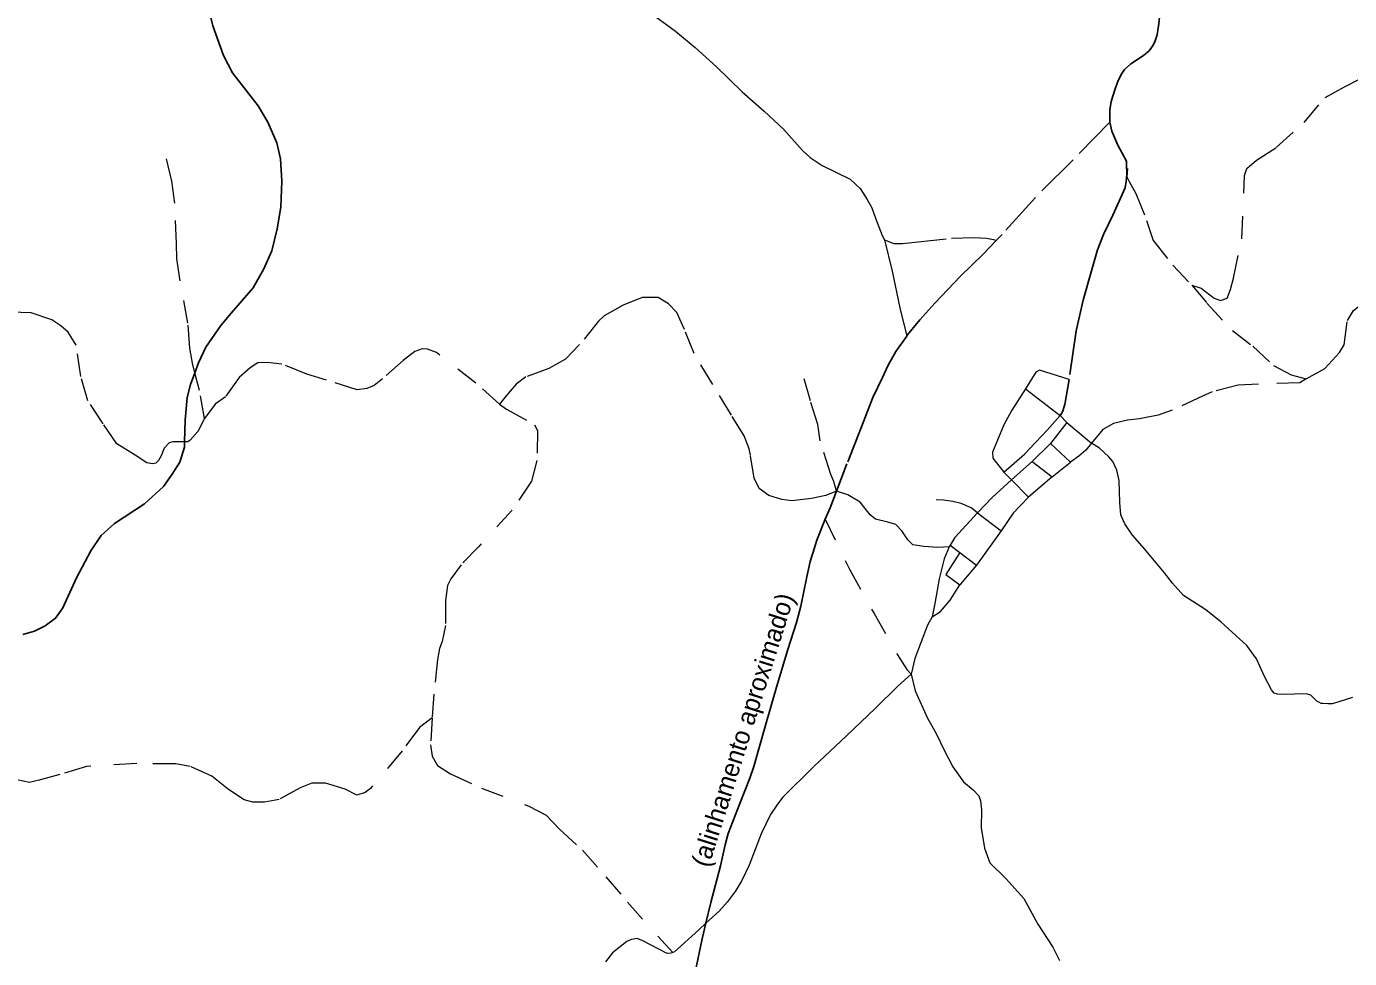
# Model space of a CAD drawing. Extents: x 703.1 to 728.9, y 7316.2 to 7344.3.
# Drawn here: x 708.41 to 714.18, y 7328.43 to 7332.5 of the extents above; entities that cross this region are included whole.
import ezdxf
from ezdxf.enums import TextEntityAlignment as Align

# ---------------------------------------------------------------- set-up
doc = ezdxf.new("R2010")
doc.units = 0
doc.header["$LTSCALE"] = 0.032
for name, pattern in [('DOTTED', [1.5, 0.3, -1.2]), ('LONG_DASHED', [7.5, 6, -1.5]), ('MEDIUM_DASHED', [4.5, 3, -1.5])]:
    doc.linetypes.add(name, pattern=pattern)
for name, color, linetype, lineweight in [('15', 7, 'Continuous', 25), ('4', 7, 'LONG_DASHED', 25), ('5', 7, 'LONG_DASHED', 13), ('6', 7, 'MEDIUM_DASHED', 13), ('7', 7, 'DOTTED', 13), ('8', 7, 'Continuous', 13)]:
    doc.layers.add(name, color=color, linetype=linetype, lineweight=lineweight)
doc.layers.add('61', color=7, linetype='Continuous')

msp = doc.modelspace()

# ---------------------------------------------------------------- linework, layer by layer
at = {"layer": '15'}
for points in [[(709.277, 7332.7781), (709.2015, 7332.6379), (709.1977, 7332.6052), (709.2236, 7332.505), (709.2701, 7332.3753), (709.3092, 7332.2997), (709.4206, 7332.1555), (709.4634, 7332.0838), (709.5024, 7331.9943), (709.5188, 7331.9238), (709.5244, 7331.8261), (709.5194, 7331.714), (709.5043, 7331.6183), (709.481, 7331.5233), (709.4457, 7331.4439), (709.3991, 7331.3608), (709.3035, 7331.2512), (709.2575, 7331.1965), (709.1933, 7331.102), (709.1606, 7331.034), (709.1445, 7330.9905)], [(709.1445, 7330.9905), (709.1259, 7330.9401), (709.1108, 7330.8834), (709.102, 7330.7839), (709.0995, 7330.6892)], [(709.0995, 7330.6892), (709.0989, 7330.6662), (709.0788, 7330.6007), (709.046, 7330.5478), (709.0083, 7330.4949), (708.9245, 7330.4188), (708.7949, 7330.3331), (708.7357, 7330.2802), (708.6904, 7330.2135), (708.628, 7330.0957), (708.5689, 7329.9647), (708.5374, 7329.9194), (708.4921, 7329.8866), (708.4448, 7329.8633), (708.3945, 7329.8482)]]:
    msp.add_lwpolyline(points, dxfattribs=at)
at = {"layer": '4'}
for points in [[(713.3572, 7332.6135), (713.3518, 7332.5254), (713.3422, 7332.4651), (713.3337, 7332.439), (713.3242, 7332.42), (713.307, 7332.3959), (713.2823, 7332.3756), (713.2278, 7332.3388), (713.1995, 7332.3134), (713.1881, 7332.2969), (713.1729, 7332.2658), (713.1589, 7332.2303), (713.1421, 7332.1744), (713.1358, 7332.1376), (713.1358, 7332.0843)], [(713.1358, 7332.0843), (712.9756, 7331.92), (712.8116, 7331.7557), (712.666, 7331.5946), (712.6412, 7331.5688)], [(713.1358, 7332.0843), (713.1448, 7332.0445), (713.1705, 7331.9832), (713.2087, 7331.914), (713.2096, 7331.8456)], [(713.2096, 7331.8456), (713.2131, 7331.882), (713.2078, 7331.827), (713.2025, 7331.7977), (713.1483, 7331.6778), (713.1088, 7331.5944), (713.0822, 7331.5269), (713.0529, 7331.4257), (713.0196, 7331.3068), (712.9895, 7331.1736), (712.958, 7330.9615)], [(712.6412, 7331.5688), (712.5819, 7331.507), (712.4842, 7331.4125), (712.3723, 7331.2938), (712.3066, 7331.2222), (712.2533, 7331.1555), (712.2501, 7331.1509)], [(712.2501, 7331.1509), (712.2029, 7331.0832), (712.1693, 7331.0236), (712.1439, 7330.9703), (712.1018, 7330.8821), (712.0631, 7330.7805), (711.9892, 7330.5934), (711.9434, 7330.4746), (711.9432, 7330.474)], [(712.958, 7330.9615), (712.9398, 7330.8514), (712.9301, 7330.8203), (712.9188, 7330.8043)], [(711.9432, 7330.474), (711.9153, 7330.4017), (711.8947, 7330.3511)], [(711.8947, 7330.3511), (711.8575, 7330.2597), (711.8398, 7330.2032), (711.829, 7330.167), (711.8138, 7330.1004), (711.7874, 7329.9716), (711.7687, 7329.9012), (711.7307, 7329.7826), (711.6815, 7329.6189), (711.6323, 7329.4475), (711.5825, 7329.2724), (711.5656, 7329.2217), (711.5219, 7329.1113), (711.4708, 7328.9799), (711.4577, 7328.9305), (711.4381, 7328.8385), (711.3952, 7328.6786), (711.3742, 7328.5886)], [(711.3742, 7328.5886), (711.3581, 7328.5199), (711.3217, 7328.3467)]]:
    msp.add_lwpolyline(points, dxfattribs=at)
at = {"layer": '5'}
for points in [[(711.112, 7332.5758), (711.2414, 7332.4815), (711.3273, 7332.4096), (711.4196, 7332.3256), (711.5315, 7332.2161), (711.6274, 7332.1322), (711.7124, 7332.0531), (711.7947, 7331.9603), (711.8291, 7331.93), (711.8806, 7331.8956), (712.0036, 7331.8357), (712.0468, 7331.7941), (712.0771, 7331.747), (712.0971, 7331.711), (712.1143, 7331.6646), (712.1423, 7331.5903), (712.1535, 7331.5711)], [(712.1535, 7331.5711), (712.1934, 7331.5543), (712.231, 7331.5543), (712.4451, 7331.5783), (712.5462, 7331.5815), (712.5982, 7331.5783), (712.6212, 7331.5732), (712.6412, 7331.5688)], [(712.1535, 7331.5711), (712.1859, 7331.4336), (712.2198, 7331.2737), (712.2501, 7331.1509)], [(714.1951, 7329.574), (714.1345, 7329.5546), (714.1059, 7329.5461), (714.0865, 7329.5461), (714.065, 7329.548), (714.0583, 7329.548), (714.0376, 7329.5595), (714.0122, 7329.5844), (713.9933, 7329.5899), (713.889, 7329.5862), (713.8677, 7329.5874), (713.8532, 7329.5923), (713.841, 7329.6069), (713.811, 7329.6651), (713.7758, 7329.7429), (713.7342, 7329.7999), (713.622, 7329.9025), (713.5549, 7329.9566), (713.4578, 7330.0185), (713.4099, 7330.0726), (713.375, 7330.1175), (713.287, 7330.2219), (713.2351, 7330.2821), (713.2011, 7330.3312), (713.1841, 7330.3701), (713.1789, 7330.4242), (713.1765, 7330.5207), (713.1665, 7330.5657), (713.1483, 7330.6027), (713.1319, 7330.624), (713.0912, 7330.6616), (713.0563, 7330.6841)], [(712.3603, 7329.9261), (712.3412, 7329.8886), (712.3125, 7329.8158), (712.2853, 7329.7444), (712.2692, 7329.676)], [(712.2692, 7329.676), (712.2118, 7329.6223), (712.1144, 7329.5266), (711.9864, 7329.4052), (711.8441, 7329.2721), (711.7084, 7329.1368), (711.6838, 7329.1037), (711.6558, 7329.0633), (711.6147, 7328.9787), (711.5629, 7328.8418), (711.5294, 7328.772), (711.5022, 7328.7271), (711.467, 7328.6807), (711.4321, 7328.6418), (711.3742, 7328.5886)], [(712.2692, 7329.676), (712.2871, 7329.6033), (712.3404, 7329.483), (712.3771, 7329.4187), (712.4129, 7329.3443), (712.4515, 7329.2709), (712.4979, 7329.2048), (712.5401, 7329.1699), (712.564, 7329.1451), (712.5722, 7329.123), (712.5768, 7329.0826), (712.575, 7329.0046), (712.5892, 7328.9155), (712.6122, 7328.8521), (712.6829, 7328.7833), (712.7614, 7328.6961), (712.822, 7328.584), (712.8867, 7328.4839), (712.917, 7328.4251)], [(711.3742, 7328.5886), (711.3431, 7328.5601), (711.2369, 7328.463), (711.2292, 7328.4601)], [(711.2292, 7328.4601), (711.2214, 7328.4572), (711.2045, 7328.4564), (711.0994, 7328.5123), (711.0748, 7328.5212), (711.0498, 7328.5175), (711.0284, 7328.5094), (710.9667, 7328.4594), (710.9365, 7328.4204)]]:
    msp.add_lwpolyline(points, dxfattribs=at)
at = {"layer": '6'}
msp.add_line((711.9434, 7330.4745), (711.9434, 7330.4746), dxfattribs=at)
for points in [[(713.4932, 7331.3736), (713.5338, 7331.3593), (713.5906, 7331.3167), (713.618, 7331.3056), (713.6484, 7331.3157), (713.6616, 7331.3543), (713.6758, 7331.404), (713.7113, 7331.5744), (713.7234, 7331.8514), (713.734, 7331.8824), (713.7756, 7331.9179), (713.8618, 7331.9737), (713.9835, 7332.0833), (714.0753, 7332.1923), (714.1595, 7332.239), (714.2223, 7332.2704), (714.2639, 7332.2917), (714.2761, 7332.31), (714.2822, 7332.3496), (714.2685, 7332.4089), (714.234, 7332.4941), (714.229, 7332.5347), (714.2401, 7332.5946), (714.27, 7332.6571)], [(713.2096, 7331.8456), (713.2206, 7331.8256), (713.2498, 7331.7723), (713.2965, 7331.6556), (713.3249, 7331.5673), (713.4101, 7331.4598), (713.4932, 7331.3736)], [(713.9916, 7330.9642), (714.074, 7331.009), (714.137, 7331.0793), (714.1576, 7331.1132), (714.1721, 7331.2186), (714.1987, 7331.2623), (714.2484, 7331.3023), (714.315, 7331.3628), (714.3992, 7331.4688), (714.4416, 7331.4906), (714.5155, 7331.5052), (714.5579, 7331.5318), (714.6063, 7331.5779), (714.6499, 7331.6336), (714.7081, 7331.6748), (714.7695, 7331.686)], [(713.4932, 7331.3736), (713.5593, 7331.2938), (713.6707, 7331.175), (713.7591, 7331.106), (713.8499, 7331.0223), (713.9262, 7330.9812), (713.9916, 7330.9642)], [(711.9432, 7330.474), (711.8973, 7330.4543), (711.8352, 7330.4418), (711.7488, 7330.4324), (711.7058, 7330.4371), (711.6482, 7330.4545), (711.606, 7330.4853), (711.5847, 7330.53), (711.5686, 7330.6316), (711.5624, 7330.6587), (711.5415, 7330.7148), (711.4856, 7330.8055), (711.4039, 7330.9399), (711.3222, 7331.0748), (711.2807, 7331.1789), (711.2467, 7331.2537), (711.2114, 7331.2914), (711.1657, 7331.3188), (711.0955, 7331.319), (711.013, 7331.2852), (710.9301, 7331.2395), (710.9053, 7331.2152), (710.8231, 7331.1136), (710.7618, 7331.0503), (710.6888, 7331.009), (710.5887, 7330.9725), (710.546, 7330.9402), (710.5023, 7330.8905), (710.4742, 7330.854)], [(709.0995, 7330.6892), (709.0484, 7330.6888), (709.033, 7330.6844), (709.0102, 7330.6615), (708.9983, 7330.6287), (708.9868, 7330.6074), (708.9744, 7330.5954), (708.96, 7330.5925), (708.9349, 7330.5982), (708.8843, 7330.6315), (708.8038, 7330.6802), (708.7445, 7330.7684), (708.6782, 7330.8685), (708.6477, 7330.9746), (708.6266, 7331.1105), (708.5926, 7331.1679), (708.5603, 7331.1957), (708.5211, 7331.2215), (708.4302, 7331.2523), (708.3401, 7331.255), (708.2472, 7331.2545), (708.1968, 7331.2503), (708.1268, 7331.2473), (708.0583, 7331.222)], [(710.4742, 7330.854), (710.371, 7330.9449), (710.1984, 7331.0788), (710.1599, 7331.093), (710.1361, 7331.0944), (710.1048, 7331.084), (710.0536, 7331.0448), (709.9635, 7330.9641), (709.9267, 7330.9348), (709.8949, 7330.9218), (709.8522, 7330.9164), (709.7184, 7330.9589), (709.6325, 7330.9852), (709.524, 7331.0287), (709.4614, 7331.0361), (709.42, 7331.0334), (709.3853, 7331.0126), (709.3376, 7330.9703), (709.2778, 7330.8856), (709.2333, 7330.8531), (709.1873, 7330.791)], [(711.9434, 7330.4746), (711.9322, 7330.5167), (711.9188, 7330.5467), (711.8727, 7330.6929), (711.862, 7330.7655), (711.8299, 7330.8676), (711.7983, 7330.9807)], [(713.9916, 7330.9642), (713.965, 7330.9472), (713.7845, 7330.9412), (713.6961, 7330.9363), (713.5823, 7330.9072), (713.5399, 7330.8891), (713.4084, 7330.8279), (713.3467, 7330.8061), (713.2655, 7330.7891), (713.2134, 7330.7831), (713.1517, 7330.7685), (713.1056, 7330.7431), (713.0563, 7330.6841)], [(710.4742, 7330.854), (710.5036, 7330.8319), (710.6258, 7330.7636), (710.6391, 7330.7391), (710.6371, 7330.6077), (710.6136, 7330.518), (710.5291, 7330.3916), (710.384, 7330.2331), (710.3061, 7330.1531), (710.2613, 7330.0909), (710.247, 7330.0624), (710.2378, 7329.9962), (710.2373, 7329.8877), (710.223, 7329.8184), (710.2123, 7329.7873), (710.2031, 7329.7394), (710.1868, 7329.5886), (710.1802, 7329.4841)], [(709.1873, 7330.791), (709.1847, 7330.7875), (709.1584, 7330.7348), (709.1239, 7330.6968), (709.114, 7330.6893), (709.0995, 7330.6892)], [(712.4344, 7330.2305), (712.3849, 7330.2279), (712.3243, 7330.2319), (712.2772, 7330.2398), (712.2543, 7330.2612), (712.2285, 7330.3004), (712.2017, 7330.3287), (712.1679, 7330.3392), (712.1143, 7330.3511), (712.0905, 7330.37), (712.0466, 7330.4254), (711.9929, 7330.4582), (711.9437, 7330.4744), (711.9434, 7330.4745)], [(711.8947, 7330.3511), (712, 7330.1342), (712.1077, 7329.9398), (712.209, 7329.7604), (712.2511, 7329.6954), (712.2692, 7329.676)], [(710.1802, 7329.4841), (710.1242, 7329.4424), (710.0488, 7329.3405), (709.9108, 7329.1769), (709.8874, 7329.1596), (709.8517, 7329.1474), (709.7998, 7329.1739), (709.7142, 7329.1994), (709.6551, 7329.1994), (709.6047, 7329.1795), (709.513, 7329.1286), (709.4478, 7329.1174), (709.3979, 7329.1174), (709.3602, 7329.1265), (709.292, 7329.1714), (709.2192, 7329.23), (709.1244, 7329.2728), (709.0613, 7329.284), (708.8912, 7329.285), (708.6717, 7329.2723), (708.5556, 7329.2376), (708.4588, 7329.2111), (708.4237, 7329.2024), (708.3676, 7329.2147)], [(710.1802, 7329.4841), (710.1729, 7329.3672), (710.1792, 7329.3173), (710.2038, 7329.2769), (710.2599, 7329.2397), (710.3953, 7329.178), (710.6018, 7329.0996), (710.6766, 7329.0596), (710.7359, 7328.9986), (710.8349, 7328.9075), (710.9374, 7328.7908), (711.0312, 7328.6803), (711.2292, 7328.4601)]]:
    msp.add_lwpolyline(points, dxfattribs=at)
at = {"layer": '7'}
for points in [[(709.1445, 7330.9905), (709.1337, 7331.032), (709.1225, 7331.098), (709.1142, 7331.2073), (709.0803, 7331.3912), (709.0661, 7331.4879), (709.0641, 7331.5545), (709.0578, 7331.7311), (709.0442, 7331.8265), (709.0169, 7331.9411)], [(709.1873, 7330.791), (709.1647, 7330.9132), (709.1445, 7330.9905)]]:
    msp.add_lwpolyline(points, dxfattribs=at)
at = {"layer": '8'}
for p, q in [((712.9477, 7330.7742), (713.0563, 7330.6841)), ((712.8768, 7330.682), (712.9639, 7330.5998)), ((712.7977, 7330.6029), (712.7076, 7330.5228)), ((712.6741, 7330.5563), (712.7076, 7330.5228)), ((712.7076, 7330.5228), (712.7805, 7330.4478)), ((712.8839, 7330.536), (712.7805, 7330.4478)), ((712.5592, 7330.3798), (712.6625, 7330.3008)), ((712.4396, 7330.2379), (712.4344, 7330.2305)), ((712.4822, 7330.2065), (712.5546, 7330.1507))]:
    msp.add_line(p, q, dxfattribs=at)
for points in [[(712.958, 7330.9615), (712.8291, 7331.0013), (712.8129, 7330.9932), (712.7683, 7330.9202), (712.9188, 7330.8043)], [(712.7683, 7330.9202), (712.7086, 7330.8269), (712.6731, 7330.7641), (712.6458, 7330.6962), (712.6235, 7330.6434), (712.6255, 7330.6181), (712.6741, 7330.5563)], [(712.6741, 7330.5563), (712.7633, 7330.6353), (712.8626, 7330.7397), (712.9188, 7330.8043), (712.9477, 7330.7742), (712.8768, 7330.682)], [(712.8768, 7330.682), (712.7977, 7330.6029), (712.8839, 7330.536), (712.9639, 7330.5998)], [(713.0563, 7330.6841), (713.0308, 7330.6526), (713.0004, 7330.6262), (712.9639, 7330.5998)], [(712.7076, 7330.5228), (712.622, 7330.4457), (712.5592, 7330.3798)], [(712.5592, 7330.3798), (712.5308, 7330.4011), (712.4872, 7330.4204), (712.4508, 7330.4285), (712.4102, 7330.4346), (712.3788, 7330.4356)], [(712.7805, 7330.4478), (712.7142, 7330.3778), (712.6625, 7330.3008)], [(712.5592, 7330.3798), (712.4599, 7330.2714), (712.4396, 7330.2379), (712.4822, 7330.2065)], [(712.6625, 7330.3008), (712.5546, 7330.1507), (712.4816, 7330.0655)], [(712.4344, 7330.2305), (712.4127, 7330.1781), (712.3915, 7330.0919), (712.3732, 7329.9844), (712.3603, 7329.9261)], [(712.4822, 7330.2065), (712.4209, 7330.1101), (712.4816, 7330.0655)], [(712.3603, 7329.9261), (712.3975, 7329.949), (712.4391, 7329.9986), (712.4816, 7330.0655)]]:
    msp.add_lwpolyline(points, dxfattribs=at)

# ---------------------------------------------------------------- texts
at = {"layer": '61'}
msp.add_text('(alinhamento aproximado)', height=0.08, rotation=72.43, dxfattribs=at).set_placement((711.573, 7329.4206), align=Align.CENTER)

doc.saveas('drawing.dxf')
